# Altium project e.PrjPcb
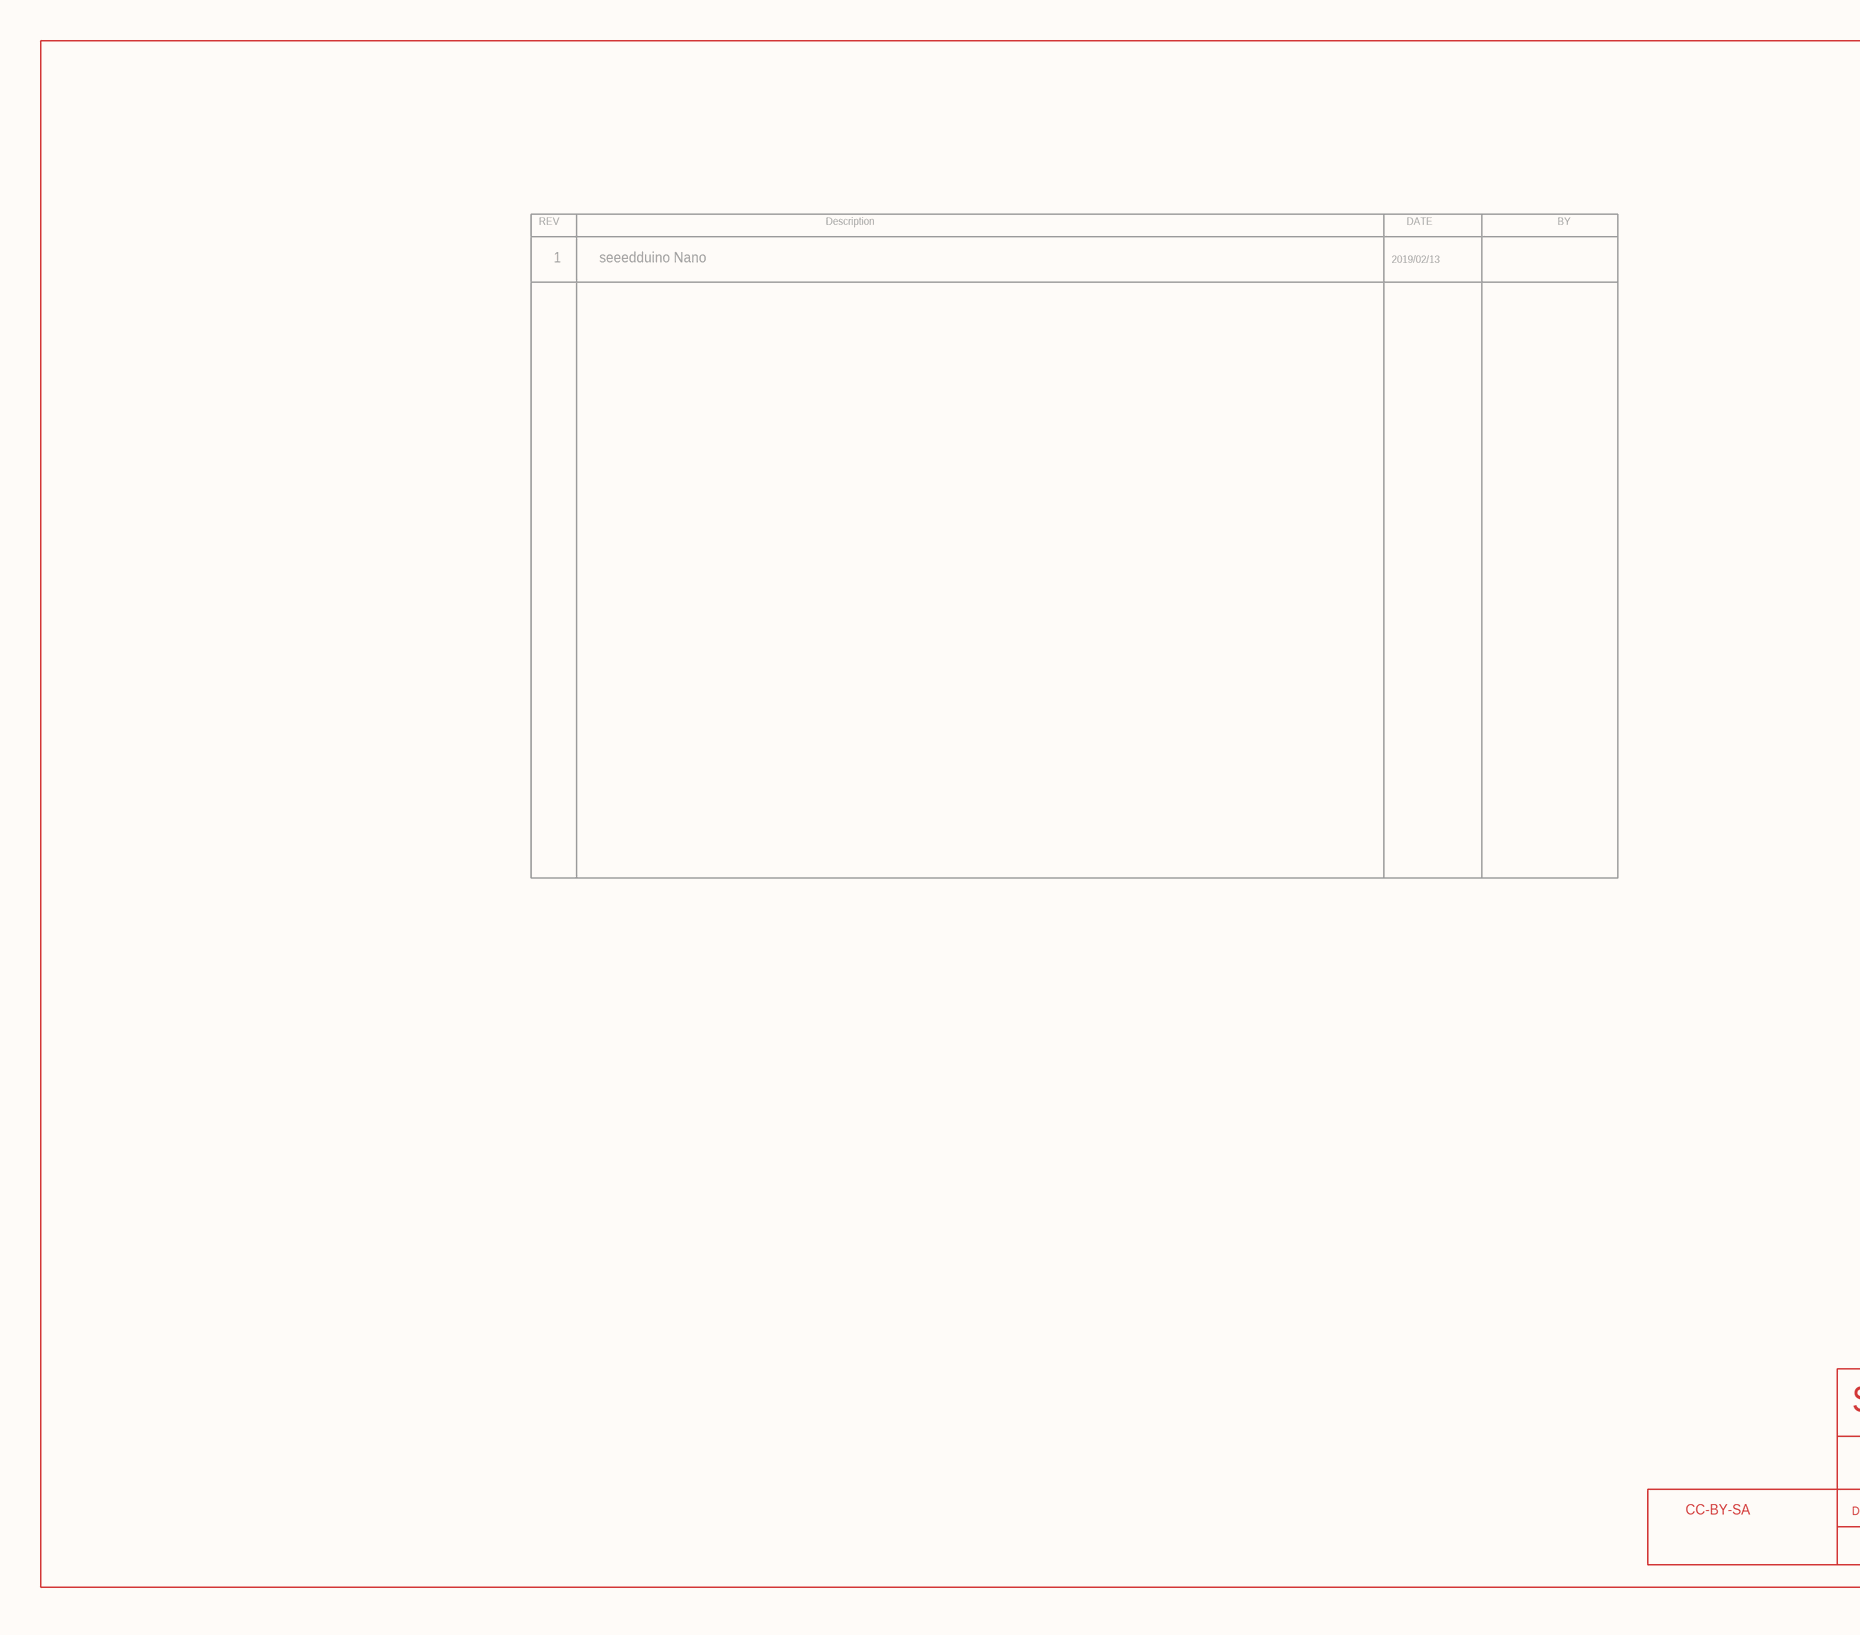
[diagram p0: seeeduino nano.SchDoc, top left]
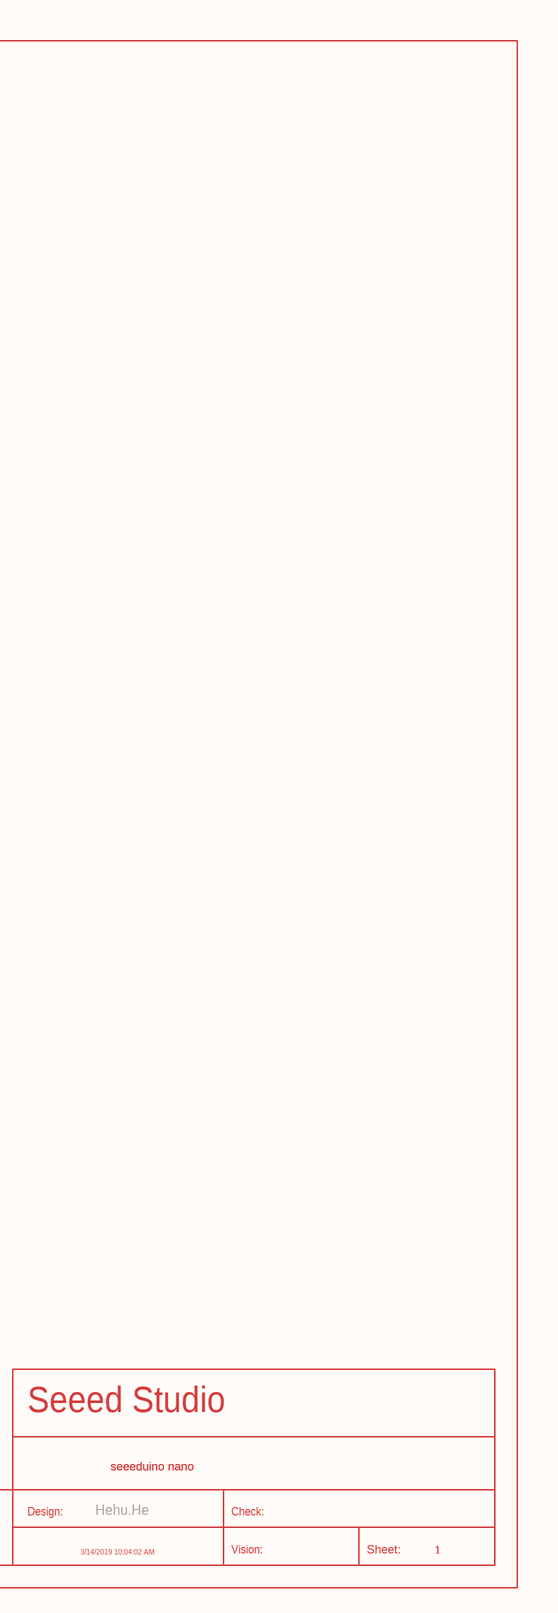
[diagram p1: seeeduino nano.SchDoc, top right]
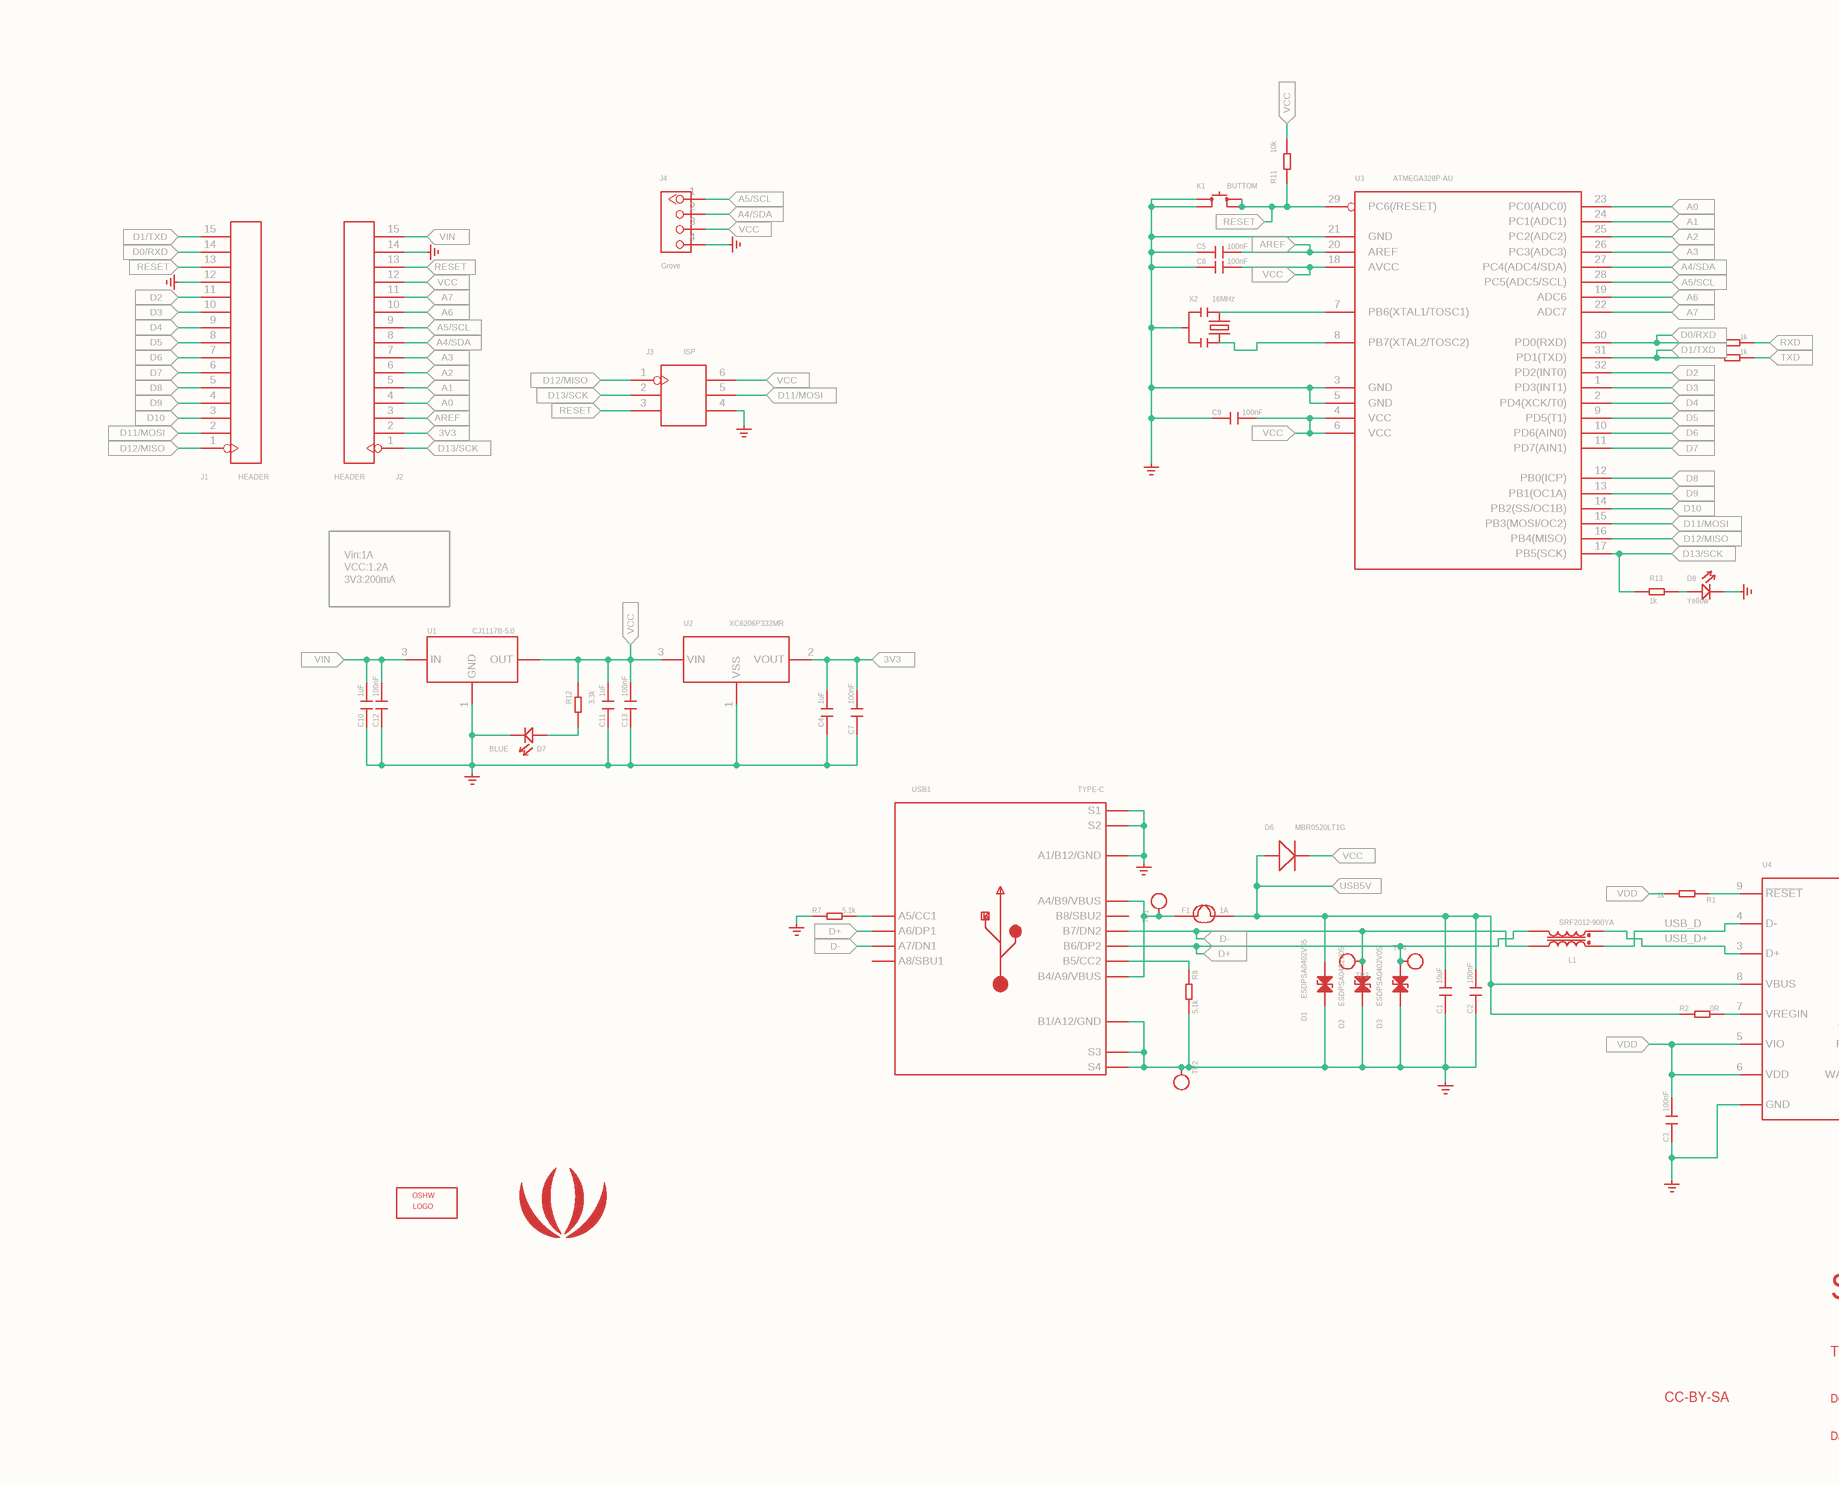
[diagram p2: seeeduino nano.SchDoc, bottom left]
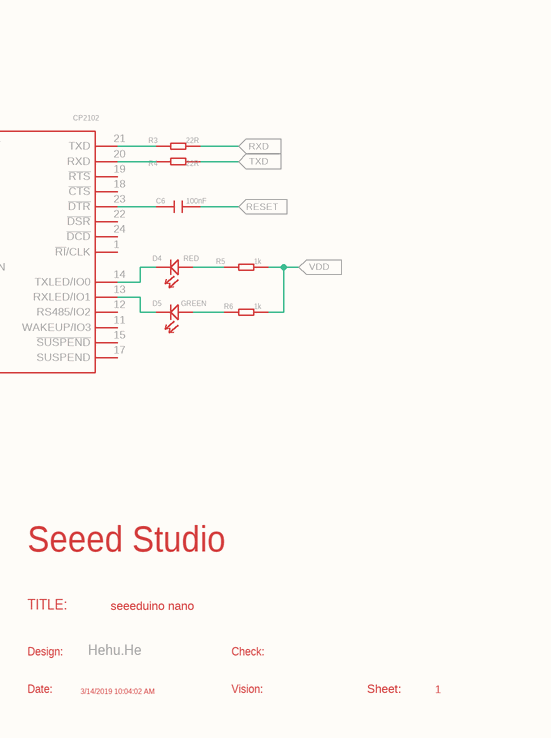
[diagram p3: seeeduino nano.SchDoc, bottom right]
1 sheet, 66 parts. Net scope: flat (ports and power ports of the same name join across sheets).
Board file: seeeduino nano.PcbDoc

## Sheet seeeduino nano.SchDoc: seeeduino nano
size custom portrait; Date: 3/14/2019 10:04:02 AM; SheetNumber: 1; Origin: Eagle; GateName_1: G$1; SymbolName_1: SEEEDSTUDIO-SCH-FRAME-BIG; LibraryName: moudle-new; DeviceSetName: SEEEDSTUDIO-SCH-FRAME-BIG; Sheet: Sheet:; SeeedStudio: Seeed Studio; Design: Design:; Check: Check:; Vision: Vision:; CC-BY-SA: CC-BY-SA

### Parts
C1  10uF  [C0603]
C2  100nF  [C0603]
C3  100nF  [C0603]
C4  1uF  [C0603]
C5  100nF  [C0603]
C6  100nF  [C0603]
C7  100nF  [C0603]
C8  100nF  [C0603]
C9  100nF  [C0603]
C10  1uF  [C0603]
C11  1uF  [C0603]
C12  100nF  [C0603]
C13  100nF  [C0603]
D1  ESDPSA0402V05  [ESD-0402]
D2  ESDPSA0402V05  [ESD-0402]
D3  ESDPSA0402V05  [ESD-0402]
D4  RED  [LED-0402]
D5  GREEN  [LED-0402]
D6  MBR0520LT1G  [SOD123-2.7X1.6]
D7  BLUE  [LED-0402]
D8  Yellow  [LED-0402]
F1  1A  [F1206]
FR2  DRAWING_NAME: seeeduino nano  SHEET: 1  Sheet: Sheet:  SeeedStudio: Seeed Studio  Design: Design:  Check: Check:  Vision: Vision:  LAST_DATE_TIME: 3/14/2019 10:04:02 AM  (hidden comment: SEEEDSTUDIO-SCH-FRAME-BIG)
G1  GND_POWER  (value not drawn)
G2  GND_POWER  (value not drawn)
G3  GND_POWER  (value not drawn)
G5  GND_POWER  (value not drawn)
G6  GND_POWER  (value not drawn)
G7  GND_POWER  (value not drawn)
G8  GND_POWER  (value not drawn)
G9  GND_POWER  (value not drawn)
G10  GND_POWER  (value not drawn)
G12  GND_POWER  (value not drawn)
G13  GND_POWER  (value not drawn)
J1  HEADER  [H15-2.54]
J2  HEADER  [H15-2.54]
J3  ISP  [H2X3-2.54]
J4  Grove  [HW4-2.0]
K1  BUTTOM  [SW4P-SMD-4.5X3.2X2.5MM]
L1  SRF2012-900YA  [INT4-0.85-2X1.25X1.2MM]
LOGO1  LOGO-OSHW-FILLX0100-NT  [OSHW_FILLX100_NOTEXT]  (value not drawn)
R1  1k  [R0603]
R2  0R  [R0603]
R3  22R  [R0603]
R4  22R  [R0603]
R5  1k  [R0603]
R6  1k  [R0603]
R7  5.1k  [R0603]
R8  5.1k  [R0603]
R9  1k  [R0603]
R10  1k  [R0603]
R11  10k  [R0603]
R12  3.3k  [R0603]
R13  1k  [R0603]
TP1  TEST  [TP-D45MIL]  (value not drawn)
TP2  TEST  [TP-D45MIL]  (value not drawn)
TP3  TEST  [TP-D45MIL]  (value not drawn)
TP4  TEST  [TP-D45MIL]  (value not drawn)
U1  CJ1117B-5.0  [SOT-223]
U2  XC6206P332MR  [SOT-23]
U3  ATMEGA328P-AU  [TQFP32-0.8-7X7MM]
U4  CP2102  [QFN24G-0.5-4X4MM]
U$1  SEEDSTUDIO-SCH-MODLIST  (value not drawn)
U$2  LOGO-SEEED-SMALL-SILK  [SEEED-SILK--TNAME-160*153MIL]  (value not drawn)
USB1  TYPE-C  [USB2.0-TYPE-C]
X2  16MHz  [RESONATOR3-SMD-3.6X1.3X0.8MM]

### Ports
3V3 (in), A0 (in), A1 (in), A2 (in), A3 (in), A4/SDA (in), A5/SCL (in), A6 (in), A7 (in), AREF (in), D0/RXD (in), D1/TXD (in), D2 (in), D3 (in), D4 (in), D5 (in), D6 (in), D7 (in), D8 (in), D9 (in), D10 (in), D11/MOSI (in), D12/MISO (in), D13/SCK (in), D+ (in), D- (in), RESET (in), RXD (in), TXD (in), USB5V (in), VCC (in), VDD (in), VIN (in)

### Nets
USB_D: L1.1 U4.4(D-)
USB_D+: L1.4 U4.3(D+)
NetC1_1: C1.1 C2.1 D1.2 D6.1(+) F1.2 R2.1 U4.8(VBUS) ; port USB5V
NetC1_2: C1.2 C2.2 D1.1 D2.1 D3.1 G2.?1(GND) R8.2 TP2.T USB1.B1_A12(B1/A12/GND) USB1.S3 USB1.S4
NetC3_1: C3.1 R1.1 R5.2 R6.2 U4.5(VIO) U4.6(VDD) ; port VDD
NetC3_2: C3.2 G3.?1(GND) U4.2_PAD(GND)
NetC4_1: C4.1 C7.1 J2.2 U2.2(VOUT) ; port 3V3
NetC4_2: C4.2 C7.2 C10.2 C11.2 C12.2 C13.2 D7.- G7.?1(GND) U1.1(GND) U2.1(VSS)
NetC5_1: C5.1 J2.3 U3.20(AREF) ; port AREF
NetC5_2: C5.2 C8.2 C9.2 G6.?1(GND) K1.1(A0) K1.2(A1) U3.3(GND) U3.5(GND) U3.21(GND) X2.2
NetC6_1: C6.1 J1.13 J2.13 J3.3 K1.3(B0) K1.4(B1) R11.1 U3.29(PC6(/RESET)) ; port RESET
NetC6_2: C6.2 U4.23(~{DTR})
NetC8_1: C8.1 C9.1 C11.1 C13.1 D6.2(-) J2.12 J3.6 J4.3 R11.2 R12.1 U1.2_TER(OUT) U2.3(VIN) U3.4(VCC) U3.6(VCC) U3.18(AVCC) ; port VCC
NetC10_1: C10.1 C12.1 J2.15 U1.3(IN) ; port VIN
NetD2_2: D2.2 L1.2 TP3.T USB1.A7(A7/DN1) USB1.B7(B7/DN2) ; port D-
NetD3_2: D3.2 L1.3 TP4.T USB1.A6(A6/DP1) USB1.B6(B6/DP2) ; port D+
NetD4_+: D4.+ R5.1
NetD4_-: D4.- U4.14(TXLED/IO0)
NetD5_+: D5.+ R6.1
NetD5_-: D5.- U4.13(RXLED/IO1)
NetD7_+: D7.+ R12.2
NetD8_+: D8.+ R13.2
NetD8_-: D8.- G8.?1(GND)
NetF1_1: F1.1 TP1.T USB1.A4_B9(A4/B9/VBUS) USB1.B4_A9(B4/A9/VBUS)
NetG1_?1: G1.?1(GND) USB1.A1_B12(A1/B12/GND) USB1.S1_S5(S1) USB1.S2_S6(S2)
NetG5_?1: G5.?1(GND) R7.1
NetG9_?1: G9.?1(GND) J2.14
NetG10_?1: G10.?1(GND) J1.12
NetG12_?1: G12.?1(GND) J3.4
NetG13_?1: G13.?1(GND) J4.4
NetJ1_1: J1.1 J3.1 U3.16(PB4(MISO)) ; port D12/MISO
NetJ1_2: J1.2 J3.5 U3.15(PB3(MOSI/OC2)) ; port D11/MOSI
NetJ1_3: J1.3 U3.14(PB2(SS/OC1B)) ; port D10
NetJ1_4: J1.4 U3.13(PB1(OC1A)) ; port D9
NetJ1_5: J1.5 U3.12(PB0(ICP)) ; port D8
NetJ1_6: J1.6 U3.11(PD7(AIN1)) ; port D7
NetJ1_7: J1.7 U3.10(PD6(AIN0)) ; port D6
NetJ1_8: J1.8 U3.9(PD5(T1)) ; port D5
NetJ1_9: J1.9 U3.2(PD4(XCK/T0)) ; port D4
NetJ1_10: J1.10 U3.1(PD3(INT1)) ; port D3
NetJ1_11: J1.11 U3.32(PD2(INT0)) ; port D2
NetJ1_14: J1.14 R9.1 U3.30(PD0(RXD)) ; port D0/RXD
NetJ1_15: J1.15 R10.1 U3.31(PD1(TXD)) ; port D1/TXD
NetJ2_1: J2.1 J3.2 R13.1 U3.17(PB5(SCK)) ; port D13/SCK
NetJ2_4: J2.4 U3.23(PC0(ADC0)) ; port A0
NetJ2_5: J2.5 U3.24(PC1(ADC1)) ; port A1
NetJ2_6: J2.6 U3.25(PC2(ADC2)) ; port A2
NetJ2_7: J2.7 U3.26(PC3(ADC3)) ; port A3
NetJ2_8: J2.8 J4.2 U3.27(PC4(ADC4/SDA)) ; port A4/SDA
NetJ2_9: J2.9 J4.1 U3.28(PC5(ADC5/SCL)) ; port A5/SCL
NetJ2_10: J2.10 U3.19(ADC6) ; port A6
NetJ2_11: J2.11 U3.22(ADC7) ; port A7
NetR1_2: R1.2 U4.9(~{RESET})
NetR2_2: R2.2 U4.7(VREGIN)
NetR3_1: R3.1 U4.21(TXD)
NetR3_2: R3.2 R9.2 ; port RXD
NetR4_1: R4.1 U4.20(RXD)
NetR4_2: R4.2 R10.2 ; port TXD
NetR7_2: R7.2 USB1.A5(A5/CC1)
NetR8_1: R8.1 USB1.B5(B5/CC2)
NetU3_7: U3.7(PB6(XTAL1/TOSC1)) X2.1
NetU3_8: U3.8(PB7(XTAL2/TOSC2)) X2.3

Not connected (* = marked no-connect by the designer): U4 1(~{RI}/CLK) 11(WAKEUP/IO3) 12(RS485/IO2) 15(~{SUSPEND}) 17(SUSPEND) 18(~{CTS}) 19(~{RTS}) 22(~{DSR}) 24(~{DCD}); USB1 A8(A8/SBU1) B8(B8/SBU2)

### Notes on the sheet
- (near U$1) 1
- seeedduino Nano
- 2019/02/13
- Hehu.He
- Vin:1A
  VCC:1.2A
  3V3:200mA
- Seeed Studio
- CC-BY-SA
- TITLE:
- Design:
- seeeduino nano
- Check:
- Date:
- 3/14/2019 10:04:02 AM
- Vision:
- Sheet:
- 1

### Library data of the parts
C1 C2 = CAP-0603: Ceramic Capacitors; GateName_1: C; DeviceName: -0603; DeviceSetName: CAP
C3-C13 = C*-0603: Ceramic Capacitors; GateName_1: C; DeviceName: -0603; DeviceSetName: C*
D1-D3 = D-ESD-2P-DOUBLE-0402: GateName_1: G$1; DeviceName: -0402
D4 D5 D7 D8 = LED-0402: GateName_1: LED; DeviceName: -0402
D6 = D*'MBR0520LT1': GateName_1: D; SymbolName_1: DIODE; DeviceSetName: D*
F1 = FUSE'1206': GateName_1: F; SymbolName_1: FUSE; DeviceName: '1206'
FR2 = SEEEDSTUDIO-SCH-FRAME-BIG: GateName_1: G$1
G1-G3 G5-G10 G12 G13 = GND_POWER: GateName_1: G$1
J1 J2 = HEADER-15P'2.54': Header 15Standard 15-pin 0.1" header. Use with straight break away headers (SKU : PRT-00116), right angle break away headers (PRT-00553), swiss pins (PRT-00743), machine pins (PRT-00117), and female headers (PRT-00115).; GateName_1: G$1; DeviceName: '2.54'
J3 = HEADER-2X3P-2.54: GateName_1: J; DeviceName: -2.54
J4 = GROVE-CONNECTOR-DIP-2.0: 4P-2.0:320110033;4P-2.0-90D:320110034; GateName_1: G$1; DeviceName: -2.0
K1 = BUTTON-4P-4.5X3.2: GateName_1: G$1; SymbolName_1: BOTTON-4P
L1 = INDUCTOR-COMMON-MODE-SRF2012-900YA: GateName_1: G$1
LOGO1 = LOGO-OSHW-FILLX0100-NT: PARTNO: DNP; GateName_1: G$1; SymbolName_1: OSHW_LOGO
R1-R13 = R*-0603: GateName_1: R; DeviceName: -0603; DeviceSetName: R*
TP1-TP4 = TEST-POINT'4545': PARTNO: DNP; GateName_1: TP; DeviceName: '4545'
U1 = PMIC-CJ*1117S: Low Drop Fixed And Adjustable Positive Voltage Regulators http://www.datasheetcatalog.org/datasheet/SGSThomsonMicroelectronics/mXuqtqv.pdf; GateName_1: G$1; DeviceName: S
U2 = PMIC-XC6206PMR: LOW ESR Cap.Compatible Positive Voltage Regulators; GateName_1: G$1; DeviceName: MR
U3 = MCU-ATMEGA8/168/328'AU': GateName_1: G$1; DeviceName: 'AU'
U4 = CONVERTER-CP2102N(QFN24): GateName_1: G$1
U$1 = SEEDSTUDIO-SCH-MODLIST: GateName_1: G$1
U$2 = LOGO-SEEED-SMALL-SILK: PARTNO: DNP; GateName_1: G$1
USB1 = USB2.0-TYPE-C: GateName_1: USB
X2 = CRYSTAL-RESONATOR: ResonatorSmall SMD resonator. This is the itty bitty 10/20MHz resonators with built in caps. CSTCE10M0G55 and CSTCE20M0V53. Footprint has been reviewed closely but hasn't been tested yet.; GateName_1: G$1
